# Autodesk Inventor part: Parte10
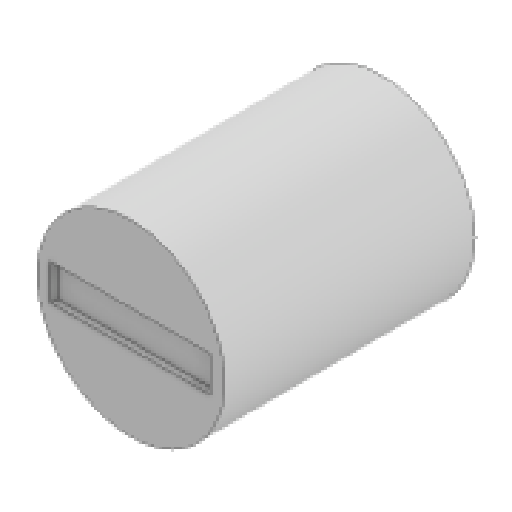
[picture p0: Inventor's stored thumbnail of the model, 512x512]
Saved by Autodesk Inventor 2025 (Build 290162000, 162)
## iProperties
Created: 2025-10
Part Number: Parte10
Material: Generico
Document SubType Name: Modeling
Designer: Ryzen5700u
Density: 1 g/cm^3
Appearance: Default
Mass: 28.1294 g
Surface Area: 52.4613 cm^2
Volume: 28.1294 cm^3
Author: Ryzen5700u
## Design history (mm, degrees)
sketch "Schizzo1"
  geometry: C1 r 15 at (0, 0); 1 further point
  constraints: 1 centre point, 1 coincident
  dimensions: "d0" = 30 diameter of C1
extrude "Estrusione1" new body sketch "Schizzo1" distance "d1" = 40; taper "d2" = 0 deg
sketch "Schizzo2"
  geometry: L1 (12.794, -2.832)-(-12.794, -2.832); L2 (-12.794, -2.832)-(-12.794, 2.832); L3 (-12.794, 2.832)-(12.794, 2.832); L4 (12.794, 2.832)-(12.794, -2.832); L5 (12.794, -2.832)-(-12.794, 2.832); L6 (-12.794, -2.832)-(12.794, 2.832); 1 further point
  constraints: 12 end point, 2 midpoint, 2 parallel, 1 horizontal, 1 perpendicular
extrude "Estrusione2" cut sketch "Schizzo2" distance "d3" = 1; taper "d4" = 0 deg
node "Solido1"
